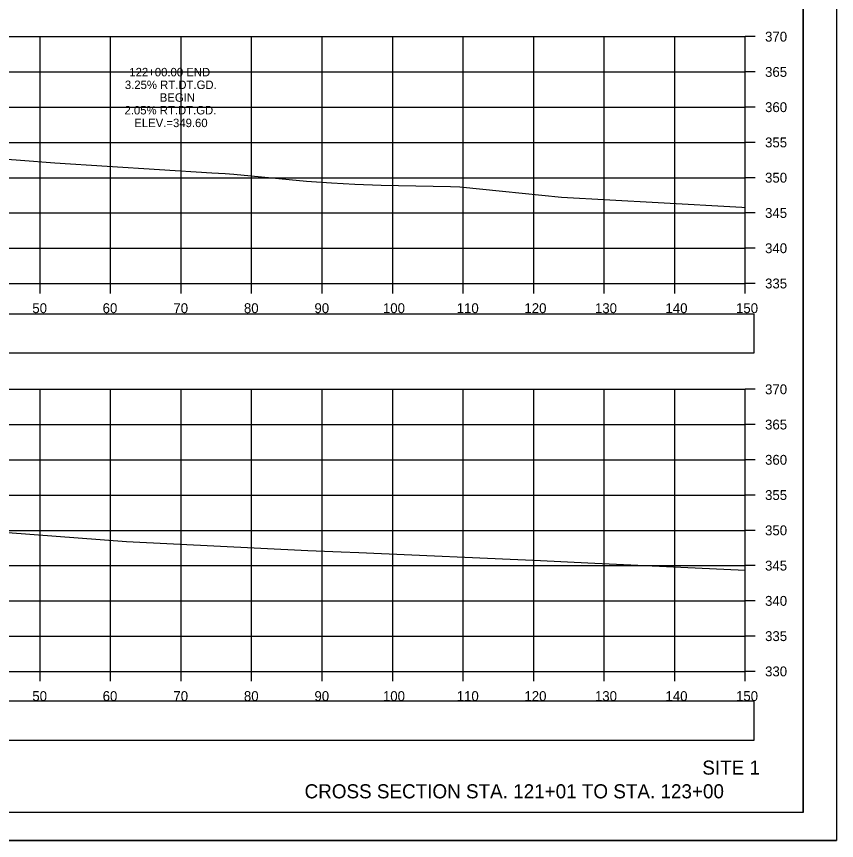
# Model space of a CAD drawing. Extents: x 1376273 to 1384221, y 378927 to 384592.
# Drawn here: x 1377104.4 to 1377220.7, y 380538.5 to 380655.3 of the extents above; entities that cross this region are included whole.
import ezdxf

# ---------------------------------------------------------------- set-up
doc = ezdxf.new("R2010")
doc.units = 0
for name, color, linetype in [('R_Axis', 7, 'Continuous'), ('R_Axis Annot', 7, 'Continuous'), ('R_Border', 7, 'Continuous'), ('R_Draft', 7, 'Continuous'), ('R_Exist Surface', 7, 'Continuous'), ('R_Grid', 7, 'Continuous'), ('R_No Plot', 7, 'Continuous'), ('R_Xsect Elev', 7, 'Continuous')]:
    doc.layers.add(name, color=color, linetype=linetype)

msp = doc.modelspace()

# ---------------------------------------------------------------- linework, layer by layer
at = {"layer": 'R_Axis'}
for p, q in [((1377207.77, 380617.49), (1377207.77, 380652.49)), ((1377209.17, 380652.49), (1377207.77, 380652.49)), ((1377209.17, 380647.49), (1377207.77, 380647.49)), ((1377209.17, 380642.49), (1377207.77, 380642.49)), ((1377209.17, 380637.49), (1377207.77, 380637.49)), ((1377209.17, 380632.49), (1377207.77, 380632.49)), ((1377209.17, 380627.49), (1377207.77, 380627.49)), ((1377209.17, 380622.49), (1377207.77, 380622.49)), ((1376907.77, 380617.49), (1377207.77, 380617.49)), ((1377107.77, 380616.09), (1377107.77, 380617.49)), ((1377117.77, 380616.09), (1377117.77, 380617.49)), ((1377127.77, 380616.09), (1377127.77, 380617.49)), ((1377137.77, 380616.09), (1377137.77, 380617.49)), ((1377147.77, 380616.09), (1377147.77, 380617.49)), ((1377157.77, 380616.09), (1377157.77, 380617.49)), ((1377167.77, 380616.09), (1377167.77, 380617.49)), ((1377177.77, 380616.09), (1377177.77, 380617.49)), ((1377187.77, 380616.09), (1377187.77, 380617.49)), ((1377197.77, 380616.09), (1377197.77, 380617.49)), ((1377207.77, 380616.09), (1377207.77, 380617.49)), ((1377209.17, 380617.49), (1377207.77, 380617.49)), ((1377207.77, 380562.49), (1377207.77, 380602.49)), ((1377209.17, 380602.49), (1377207.77, 380602.49)), ((1377209.17, 380597.49), (1377207.77, 380597.49)), ((1377209.17, 380592.49), (1377207.77, 380592.49)), ((1377209.17, 380587.49), (1377207.77, 380587.49)), ((1377209.17, 380582.49), (1377207.77, 380582.49)), ((1377209.17, 380577.49), (1377207.77, 380577.49)), ((1377209.17, 380572.49), (1377207.77, 380572.49)), ((1377209.17, 380567.49), (1377207.77, 380567.49)), ((1376907.77, 380562.49), (1377207.77, 380562.49)), ((1377107.77, 380561.09), (1377107.77, 380562.49)), ((1377117.77, 380561.09), (1377117.77, 380562.49)), ((1377127.77, 380561.09), (1377127.77, 380562.49)), ((1377137.77, 380561.09), (1377137.77, 380562.49)), ((1377147.77, 380561.09), (1377147.77, 380562.49)), ((1377157.77, 380561.09), (1377157.77, 380562.49)), ((1377167.77, 380561.09), (1377167.77, 380562.49)), ((1377177.77, 380561.09), (1377177.77, 380562.49)), ((1377187.77, 380561.09), (1377187.77, 380562.49)), ((1377197.77, 380561.09), (1377197.77, 380562.49)), ((1377207.77, 380561.09), (1377207.77, 380562.49)), ((1377209.17, 380562.49), (1377207.77, 380562.49))]:
    msp.add_line(p, q, dxfattribs=at)
at = {"layer": 'R_Axis Annot'}
for points in [[(1376907.2, 380607.64), (1377209.01, 380607.64), (1377209.01, 380613.16), (1376907.2, 380613.16)], [(1376907.2, 380552.73), (1377209.01, 380552.73), (1377209.01, 380558.25), (1376907.2, 380558.25)]]:
    msp.add_lwpolyline(points, close=True, dxfattribs=at)
at = {"layer": 'R_Border'}
for q in [(1377215.95, 380747.95), (1376899.77, 380542.49)]:
    msp.add_line((1377215.95, 380542.49), q, dxfattribs=at)
at = {"layer": 'R_Exist Surface'}
for points in [[(1377101.8, 380635.2), (1377105.02, 380634.98), (1377109.89, 380634.59), (1377132.14, 380633.2), (1377134.01, 380633.09), (1377135.25, 380632.97), (1377145.57, 380632.02), (1377149.08, 380631.75), (1377152.39, 380631.59), (1377156.12, 380631.41), (1377165.96, 380631.25), (1377167.3, 380631.2), (1377173.35, 380630.56), (1377181.69, 380629.74), (1377195.39, 380628.99), (1377207.26, 380628.29), (1377207.77, 380628.28)], [(1377103.2, 380582.18), (1377120.04, 380580.92), (1377145.74, 380579.65), (1377150.49, 380579.45), (1377152.95, 380579.34), (1377178.74, 380578.22), (1377185.46, 380577.9), (1377207.77, 380576.85)]]:
    msp.add_lwpolyline(points, dxfattribs=at)
at = {"layer": 'R_Grid'}
for p, q in [((1376907.77, 380652.49), (1377207.77, 380652.49)), ((1376907.77, 380652.49), (1377207.77, 380652.49)), ((1377107.77, 380617.49), (1377107.77, 380652.49)), ((1377107.77, 380617.49), (1377107.77, 380652.49)), ((1377117.77, 380617.49), (1377117.77, 380652.49)), ((1377117.77, 380617.49), (1377117.77, 380652.49)), ((1377127.77, 380617.49), (1377127.77, 380652.49)), ((1377127.77, 380617.49), (1377127.77, 380652.49)), ((1377137.77, 380617.49), (1377137.77, 380652.49)), ((1377137.77, 380617.49), (1377137.77, 380652.49)), ((1377147.77, 380617.49), (1377147.77, 380652.49)), ((1377147.77, 380617.49), (1377147.77, 380652.49)), ((1377157.77, 380617.49), (1377157.77, 380652.49)), ((1377157.77, 380617.49), (1377157.77, 380652.49)), ((1377167.77, 380617.49), (1377167.77, 380652.49)), ((1377167.77, 380617.49), (1377167.77, 380652.49)), ((1377177.77, 380617.49), (1377177.77, 380652.49)), ((1377177.77, 380617.49), (1377177.77, 380652.49)), ((1377187.77, 380617.49), (1377187.77, 380652.49)), ((1377187.77, 380617.49), (1377187.77, 380652.49)), ((1377197.77, 380617.49), (1377197.77, 380652.49)), ((1377197.77, 380617.49), (1377197.77, 380652.49)), ((1377207.77, 380617.49), (1377207.77, 380652.49)), ((1377207.77, 380617.49), (1377207.77, 380652.49)), ((1376907.77, 380647.49), (1377207.77, 380647.49)), ((1376907.77, 380647.49), (1377207.77, 380647.49)), ((1376907.77, 380642.49), (1377207.77, 380642.49)), ((1376907.77, 380642.49), (1377207.77, 380642.49)), ((1376907.77, 380637.49), (1377207.77, 380637.49)), ((1376907.77, 380637.49), (1377207.77, 380637.49)), ((1376907.77, 380632.49), (1377207.77, 380632.49)), ((1376907.77, 380632.49), (1377207.77, 380632.49)), ((1376907.77, 380627.49), (1377207.77, 380627.49)), ((1376907.77, 380627.49), (1377207.77, 380627.49)), ((1376907.77, 380622.49), (1377207.77, 380622.49)), ((1376907.77, 380622.49), (1377207.77, 380622.49)), ((1376907.77, 380617.49), (1377207.77, 380617.49)), ((1376907.77, 380617.49), (1377207.77, 380617.49)), ((1376907.77, 380602.49), (1377207.77, 380602.49)), ((1376907.77, 380602.49), (1377207.77, 380602.49)), ((1377107.77, 380562.49), (1377107.77, 380602.49)), ((1377107.77, 380562.49), (1377107.77, 380602.49)), ((1377117.77, 380562.49), (1377117.77, 380602.49)), ((1377117.77, 380562.49), (1377117.77, 380602.49)), ((1377127.77, 380562.49), (1377127.77, 380602.49)), ((1377127.77, 380562.49), (1377127.77, 380602.49)), ((1377137.77, 380562.49), (1377137.77, 380602.49)), ((1377137.77, 380562.49), (1377137.77, 380602.49)), ((1377147.77, 380562.49), (1377147.77, 380602.49)), ((1377147.77, 380562.49), (1377147.77, 380602.49)), ((1377157.77, 380562.49), (1377157.77, 380602.49)), ((1377157.77, 380562.49), (1377157.77, 380602.49)), ((1377167.77, 380562.49), (1377167.77, 380602.49)), ((1377167.77, 380562.49), (1377167.77, 380602.49)), ((1377177.77, 380562.49), (1377177.77, 380602.49)), ((1377177.77, 380562.49), (1377177.77, 380602.49)), ((1377187.77, 380562.49), (1377187.77, 380602.49)), ((1377187.77, 380562.49), (1377187.77, 380602.49)), ((1377197.77, 380562.49), (1377197.77, 380602.49)), ((1377197.77, 380562.49), (1377197.77, 380602.49)), ((1377207.77, 380562.49), (1377207.77, 380602.49)), ((1377207.77, 380562.49), (1377207.77, 380602.49)), ((1376907.77, 380597.49), (1377207.77, 380597.49)), ((1376907.77, 380597.49), (1377207.77, 380597.49)), ((1376907.77, 380592.49), (1377207.77, 380592.49)), ((1376907.77, 380592.49), (1377207.77, 380592.49)), ((1376907.77, 380587.49), (1377207.77, 380587.49)), ((1376907.77, 380587.49), (1377207.77, 380587.49)), ((1376907.77, 380582.49), (1377207.77, 380582.49)), ((1376907.77, 380582.49), (1377207.77, 380582.49)), ((1376907.77, 380577.49), (1377207.77, 380577.49)), ((1376907.77, 380577.49), (1377207.77, 380577.49)), ((1376907.77, 380572.49), (1377207.77, 380572.49)), ((1376907.77, 380572.49), (1377207.77, 380572.49)), ((1376907.77, 380567.49), (1377207.77, 380567.49)), ((1376907.77, 380567.49), (1377207.77, 380567.49)), ((1376907.77, 380562.49), (1377207.77, 380562.49)), ((1376907.77, 380562.49), (1377207.77, 380562.49))]:
    msp.add_line(p, q, dxfattribs=at)
at = {"layer": 'R_No Plot'}
msp.add_line((1376887.37, 380538.52), (1377220.7, 380538.52), dxfattribs=at)
for points in [[(1376887.36, 380751.85), (1377220.7, 380751.85), (1377220.7, 380538.51), (1376887.36, 380538.51)], [(1377133.69, 380747.95), (1377133.69, 380738.07), (1377169.42, 380738.07), (1377169.42, 380735.15), (1377192.62, 380735.15), (1377192.62, 380710.82), (1377215.95, 380710.82), (1377215.95, 380542.49), (1376899.77, 380542.49), (1376899.77, 380747.95)]]:
    msp.add_lwpolyline(points, close=True, dxfattribs=at)

# ---------------------------------------------------------------- texts
at = {"layer": 'R_Axis Annot'}
for s, p in [('370', (1377210.57, 380651.79)), ('365', (1377210.57, 380646.79)), ('360', (1377210.57, 380641.79)), ('355', (1377210.57, 380636.79)), ('350', (1377210.57, 380631.79)), ('345', (1377210.57, 380626.79)), ('340', (1377210.57, 380621.79)), ('335', (1377210.57, 380616.79)), ('50', (1377106.68, 380613.29)), ('60', (1377116.65, 380613.29)), ('70', (1377126.68, 380613.29)), ('80', (1377136.68, 380613.29)), ('90', (1377146.68, 380613.29)), ('100', (1377156.39, 380613.29)), ('110', (1377166.85, 380613.29)), ('120', (1377176.45, 380613.29)), ('130', (1377186.45, 380613.29)), ('140', (1377196.45, 380613.29)), ('150', (1377206.45, 380613.29)), ('370', (1377210.57, 380601.79)), ('365', (1377210.57, 380596.79)), ('360', (1377210.57, 380591.79)), ('355', (1377210.57, 380586.79)), ('350', (1377210.57, 380581.79)), ('345', (1377210.57, 380576.79)), ('340', (1377210.57, 380571.79)), ('335', (1377210.57, 380566.79)), ('330', (1377210.57, 380561.79)), ('50', (1377106.68, 380558.29)), ('60', (1377116.65, 380558.29)), ('70', (1377126.68, 380558.29)), ('80', (1377136.68, 380558.29)), ('90', (1377146.68, 380558.29)), ('100', (1377156.39, 380558.29)), ('110', (1377166.85, 380558.29)), ('120', (1377176.45, 380558.29)), ('130', (1377186.45, 380558.29)), ('140', (1377196.45, 380558.29)), ('150', (1377206.45, 380558.29))]:
    msp.add_text(s, height=1.4, dxfattribs=at).set_placement(p)
at = {"layer": 'R_Draft'}
for s, p in [('SITE 1', (1377201.67, 380547.85)), ('CROSS SECTION STA. 121+01 TO STA. 123+00', (1377145.28, 380544.49))]:
    msp.add_text(s, height=2, dxfattribs=at).set_placement(p)
at = {"layer": 'R_Xsect Elev'}
for s, p in [('122+00.00 END', (1377120.43, 380646.86)), ('3.25% RT.DT.GD.', (1377119.8, 380645.06)), ('BEGIN', (1377124.75, 380643.26)), ('2.05% RT.DT.GD.', (1377119.75, 380641.46)), ('ELEV.=349.60', (1377121.14, 380639.66))]:
    msp.add_text(s, height=1.2, rotation=360, dxfattribs=at).set_placement(p)

doc.saveas('drawing.dxf')
